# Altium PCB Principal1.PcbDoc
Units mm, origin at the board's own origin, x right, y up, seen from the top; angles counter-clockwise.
Board outline 152.4 x 101.6 mm, 2 copper layers (Top Layer, Bottom Layer); 36 components, 54 nets, 182 pads, 5 vias.
Unrouted connection lines stored in the file: 82.
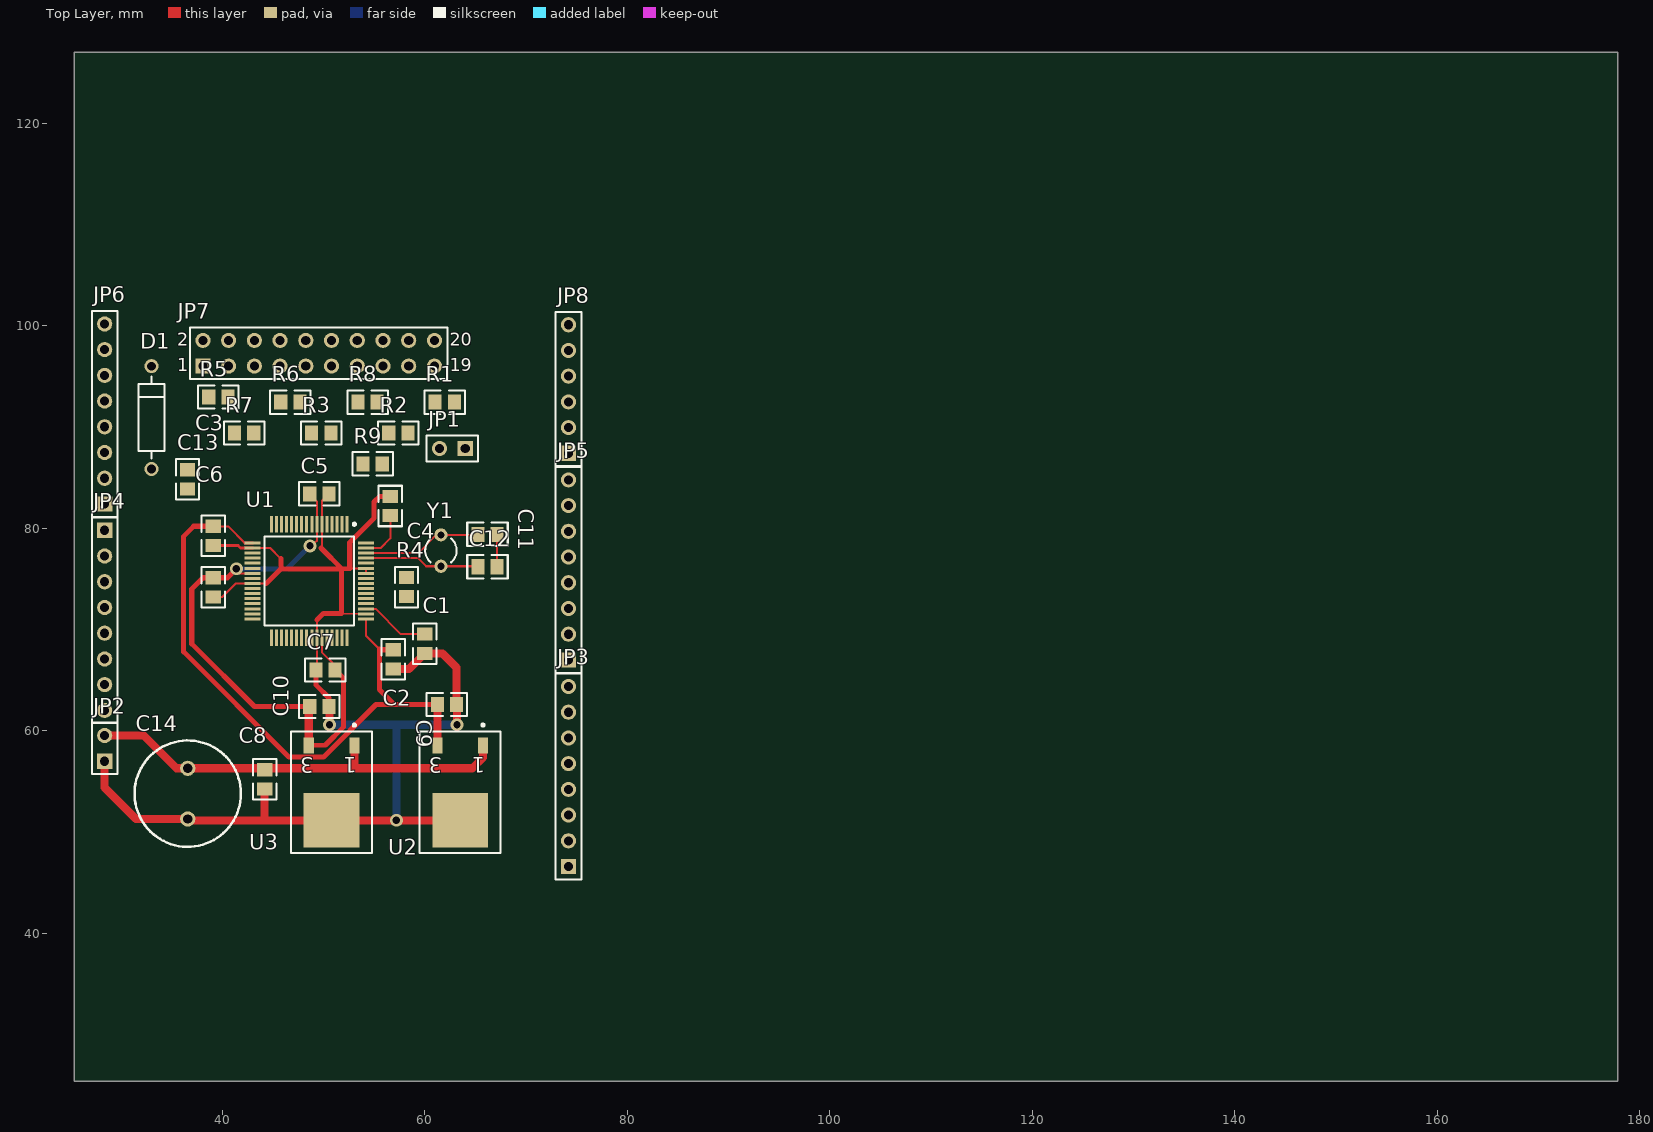
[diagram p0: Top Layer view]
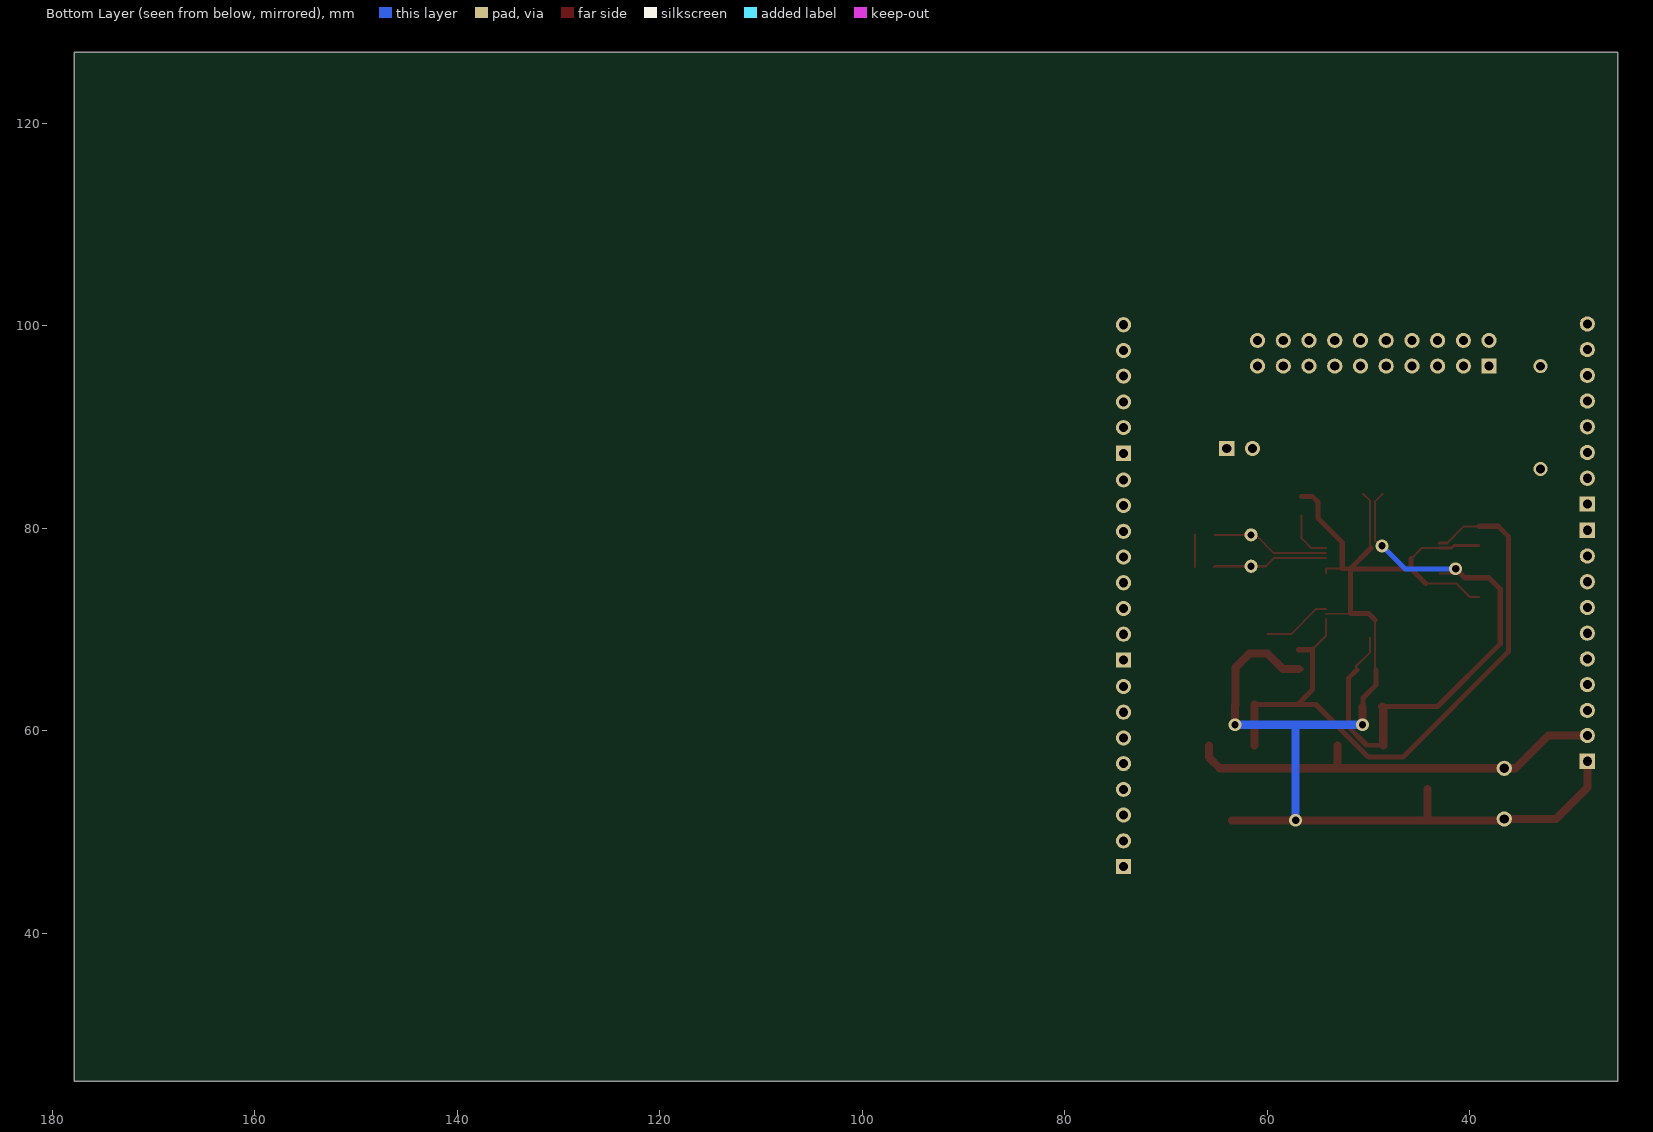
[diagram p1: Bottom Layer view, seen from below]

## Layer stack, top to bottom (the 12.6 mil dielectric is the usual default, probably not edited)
Top Layer: signal copper 0.0356
Dielectric: dielectric 0.32, FR-4, Dk 4.8
Bottom Layer: signal copper 0.0356

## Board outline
25.4,25.4 177.8,25.4 177.8,127 25.4,127

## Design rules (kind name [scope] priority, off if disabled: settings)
Clearance [All] p1: gap=0.1
ComponentClearance [All] p1: gap=0.254 collisioncheckmode=0
PolygonConnect [All] p1: connectstyle=Relief reliefconductorwidth=0.254 reliefentries=4 polygonreliefangle="90 Angle"
RoomDefinition Principal [InComponentClass('Principal')] p1: confinementstyle=ConfineIn formatcopy=TRUE outline 26.416,35.052 140.716,35.052 140.716,122.936 26.416,122.936
RoutingLayers [All] p1: top layer=Horizontal bottom layer=Vertical
RoutingVias [All] p1: holewidth=0.711 width=1.27 viastyle="Through Hole" minholewidth=0.711 minwidth=1.27 maxholewidth=0.711 maxwidth=1.27
SolderMaskExpansion [All] p1: expansion=0.102
TestPointUsage [All] p1: valid=0 allowmultiple=FALSE
Testpoint [All] p1: side=15 testpointundercomponent=TRUE minsize=1.016 maxsize=2.54 preferedsize=1.524 minholesize=0 maxholesize=1.016 preferedholesize=0.813 testpointgrid=0.025 style=1023 order=-539222988
Width [All] p1: maxlimit=0.8 minlimit=0.2 preferedwidth=0.2 bottomlayer_prefwidth=0.8 minimp=50.000000 maximp=50.000000 favimp=50.000000
16 further rules are at their usual default settings.

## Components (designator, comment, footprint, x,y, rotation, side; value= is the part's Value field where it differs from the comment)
C1 "Cap" R2012-0805 56.6,82.2 r270 top
C2 "Cap" R2012-0805 56.896,67.056 r90 top
C3 "Cap" R2012-0805 39.116,79.248 r90 top
C4 "Cap" R2012-0805 60,68.6 r90 top
C5 "Cap" R2012-0805 49.6,83.4 r180 top
C6 "Cap" R2012-0805 39.116,74.168 r90 top
C7 "Cap" R2012-0805 50.2,66 r0 top
C8 "Cap" R2012-0805 44.2,55.2 r90 top
C9 "Cap" R2012-0805 62.2,62.6 r180 top
C10 "Cap" R2012-0805 49.6,62.4 r180 top
C11 "Cap" R2012-0805 66.2,79.4 r0 top
C12 "Cap" R2012-0805 66.2,76.2 r0 top
C13 "Cap" R2012-0805 36.576,84.836 r270 top
C14 "Cap Pol1" RB5-10.5 36.6,53.8 r270 top
D1 "Diode" DIODE-0.4 33.02,90.932 r90 top
JP1 "JTAG" HDR1X2 64.008,87.884 r180 top
JP2 "Header 2" HDR1X2 28.4,57 r90 top
JP3 "Header 8" HDR1X8 74.2,46.6 r90 top
JP4 "Header 8" HDR1X8 28.4,79.8 r270 top
JP5 "Header 8" HDR1X8 74.2,67 r90 top
JP6 "Header 8" HDR1X8 28.4,82.4 r90 top
JP7 "JTAG P5" HDR2X10 38.1,96.012 r0 top
JP8 "Header 6" HDR1X6 74.2,87.4 r90 top
R1 "Res1" R2012-0805 61.976,92.456 r0 top
R2 "Res1" R2012-0805 57.404,89.408 r180 top
R3 "Res1" R2012-0805 49.784,89.408 r180 top
R4 "Res1" R2012-0805 58.2,74.2 r90 top
R5 "Res1" R2012-0805 39.624,92.964 r0 top
R6 "Res1" R2012-0805 46.736,92.456 r180 top
R7 "Res1" R2012-0805 42.164,89.408 r0 top
R8 "Res1" R2012-0805 54.356,92.456 r180 top
R9 "Res1" R2012-0805 54.864,86.36 r180 top
U1 "LPC2114/LPC2124" F-QFP10X10-G64/N 48.6,74.8 r270 top
U2 "LD1117S18" SIP-G3/C7.4 63.5,54.864 r180 top
U3 "LD1117S33" SIP-G3/C7.4 50.8,54.864 r180 top
Y1 "XTAL 16Mhz" BCY-W2/D3.1 61.6,77.8 r180 top

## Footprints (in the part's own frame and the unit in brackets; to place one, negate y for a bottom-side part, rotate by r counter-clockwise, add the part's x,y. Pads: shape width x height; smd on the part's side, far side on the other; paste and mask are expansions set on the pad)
BCY-W2/D3.1 [mm]
  round 1.3 hole 0.7: 1(0,1.55) 2(0,-1.55)
  silkscreen extent -1.55,-1.19 1.55,1.17
DIODE-0.4 [mm]
  round 1.4 hole 0.85: 1(-5.08,0) 2(5.08,0)
  silkscreen extent -4.06,-1.27 4.06,1.27
F-QFP10X10-G64/N [mm]
  rect 1.6x0.3 smd: 1(-5.6,3.75) 2(-5.6,3.25) 3(-5.6,2.75) 4(-5.6,2.25) 5(-5.6,1.75) 6(-5.6,1.25) 7(-5.6,0.75) 8(-5.6,0.25) 9(-5.6,-0.25) 10(-5.6,-0.75) 11(-5.6,-1.25) 12(-5.6,-1.75) 13(-5.6,-2.25) 14(-5.6,-2.75) 15(-5.6,-3.25) 16(-5.6,-3.75) 33(5.6,-3.75) 34(5.6,-3.25) 35(5.6,-2.75) 36(5.6,-2.25) 37(5.6,-1.75) 38(5.6,-1.25) 39(5.6,-0.75) 40(5.6,-0.25) 41(5.6,0.25) 42(5.6,0.75) 43(5.6,1.25) 44(5.6,1.75) 45(5.6,2.25) 46(5.6,2.75) 47(5.6,3.25) 48(5.6,3.75)
  rect 0.3x1.6 smd: 17(-3.75,-5.6) 18(-3.25,-5.6) 19(-2.75,-5.6) 20(-2.25,-5.6) 21(-1.75,-5.6) 22(-1.25,-5.6) 23(-0.75,-5.6) 24(-0.25,-5.6) 25(0.25,-5.6) 26(0.75,-5.6) 27(1.25,-5.6) 28(1.75,-5.6) 29(2.25,-5.6) 30(2.75,-5.6) 31(3.25,-5.6) 32(3.75,-5.6) 49(3.75,5.6) 50(3.25,5.6) 51(2.75,5.6) 52(2.25,5.6) 53(1.75,5.6) 54(1.25,5.6) 55(0.75,5.6) 56(0.25,5.6) 57(-0.25,5.6) 58(-0.75,5.6) 59(-1.25,5.6) 60(-1.75,5.6) 61(-2.25,5.6) 62(-2.75,5.6) 63(-3.25,5.6) 64(-3.75,5.6)
  silkscreen extent -5.72,-4.4 4.4,4.58
HDR1X2 [mm]
  rect 1.5x1.5 hole 0.9: 1(0,0)
  round 1.5 hole 0.9: 2(2.54,0)
  silkscreen extent -1.27,-1.27 3.81,1.27
HDR1X6 [mm]
  rect 1.5x1.5 hole 0.9: 1(0,0)
  round 1.5 hole 0.9: 2(2.54,0) 3(5.08,0) 4(7.62,0) 5(10.16,0) 6(12.7,0)
  silkscreen extent -1.27,-1.27 13.97,1.27
HDR1X8 [mm]
  rect 1.5x1.5 hole 0.9: 1(0,0)
  round 1.5 hole 0.9: 2(2.54,0) 3(5.08,0) 4(7.62,0) 5(10.16,0) 6(12.7,0) 7(15.24,0) 8(17.78,0)
  silkscreen extent -1.27,-1.27 19.05,1.27
HDR2X10 [mm]
  rect 1.5x1.5 hole 0.9: 1(0,0)
  round 1.5 hole 0.9: 2(0,2.54) 3(2.54,0) 4(2.54,2.54) 5(5.08,0) 6(5.08,2.54) 7(7.62,0) 8(7.62,2.54) 9(10.16,0) 10(10.16,2.54) 11(12.7,0) 12(12.7,2.54) 13(15.24,0) 14(15.24,2.54) 15(17.78,0) 16(17.78,2.54) 17(20.32,0) 18(20.32,2.54) 19(22.86,0) 20(22.86,2.54)
  silkscreen extent -1.27,-1.27 24.13,3.81
R2012-0805 [mm]
  rect 1.3x1.5 smd: 1(-0.95,0) 2(0.95,0)
  silkscreen extent -2,-1.15 2,1.15
RB5-10.5 [mm]
  round 1.5 hole 0.9: 1(-2.5,0) 2(2.5,0)
  silkscreen extent -5.25,-5.25 5.25,5.25
SIP-G3/C7.4 [mm]
  rect 1x1.6 smd: 1(-2.25,-3.7) 3(2.25,-3.7)
  rect 5.5x5.4 smd: 4(0,3.7)
  silkscreen extent -4,-5.82 4,6.95

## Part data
C1 C2 C3 C4 C5 C6 C7 C8 C9 C10 C11 C12 C13: "Capacitor"
C14: "Polarized Capacitor (Radial)"
D1: "Default Diode"
JP1: library part "Header 2", "Header, 2-Pin"
JP2: "Header, 2-Pin"
JP3 JP4 JP5 JP6: "Header, 8-Pin"
JP7: library part "Header 10X2", "Header, 10-Pin, Dual row"
JP8: "Header, 6-Pin"
R1 R2 R3 R4 R5 R6 R7 R8 R9: "Resistor"
U2 U3: library part LF27ACDT, "Very Low Drop Voltage Regulator with Inhibit"
Y1: library part XTAL, "Crystal Oscillator"

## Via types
v1: diameter 1.27, hole 0.711, Top Layer to Bottom Layer, 5 vias

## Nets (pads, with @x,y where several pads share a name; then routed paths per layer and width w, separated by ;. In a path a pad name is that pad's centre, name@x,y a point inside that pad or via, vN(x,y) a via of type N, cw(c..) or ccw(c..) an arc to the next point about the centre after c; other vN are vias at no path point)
GND: C1.1 C2.1 C3.1 C4.1 C5.1 C6.1 C7.1 C8.1 C9.1 C10.1 C11.2 C12.2 C13.2 C14.2 JP1.1 JP2.1 JP7.4 JP7.6 JP7.8 JP7.10 JP7.12 JP7.14 JP7.16 JP7.18 JP7.20 R1.2 R2.2 R3.2 U1.6 U1.18 U1.25 U1.42 U1.50 U1.58 U1.59 U2.4 U3.4 | length 143.9
  Top Layer w0.2: C6.1 40.018,73.218 41.35,74.55 44.35,74.55 ; U1.18 44.75,78.05 45.8,77 ; C7.1@49.342,66.04 49.35,66.048 49.35,70.95 ; 49.85,77.95 49.85,82.7 C5.1 ; 51.8,71.6 U1.50 ; 52.6,76.05 U1.59 U1.58 ; C2.1@56.494,66.106 C2.1 ; C12.2 C11.2
  Top Layer w0.254: C3.1 41.571,78.298 41.819,78.05 U1.18
  Top Layer w0.5: 44.35,74.55 45.8,76 ; 45.8,77 45.8,76 ; C7.1 49.25,64.55 50.55,63.25 C10.1 ; 49.35,70.95 50,71.6 51.8,71.6 51.8,76 ; 49.75,78.05 49.85,77.95 51.8,76 ; C1.1 55.55,83.15 55,82.6 55,81 52.6,78.6 52.6,76.05 51.8,76 ; 45.8,76 51.8,76
  Top Layer w0.8: JP2.1 28.4,54.4 31.5,51.3 C14.2 36.736,51.164 U2.4 ; 44.2,51.364 C8.1 ; v1(50.6,60.6) C10.1@50.6,62.35 ; C2.1 58.456,66.106 C4.1 61.75,67.65 63.15,66.25 C9.1 ; v1(63.2,60.6) C9.1@63.2,62.55
  Bottom Layer w0.8: v1(50.6,60.6) v1(63.2,60.6) ; v1(57.2,51.164) 57.2,60.6
NetC1_2: C1.2 C2.2 C3.2 C9.2 U1.17 U1.49 U1.63 U2.3 | length 70.9
  Top Layer w0.2: C3.2 40.602,80.198 U1.17@42.25,78.55 ; U1.49 54.2,69.4 55.521,68.079 ; U1.63 55.65,78.05 56.6,79 C1.2
  Top Layer w0.254: U1.17@42.25,78.55 U1.17
  Top Layer w0.5: C3.2 37.198,80.198 36.2,79.2 36.2,67.8 46.6,57.4 50,57.4 55.2,62.6 C9.2 ; C2.2 55.594,68.006 55.521,68.079 55.521,64.079 57,62.6
  Top Layer w0.8: U2.3 C9.2
NetC4_2: C4.2 C5.2 C6.2 C7.2 C10.2 D1.2 JP7.1 JP7.2 R5.1 R6.1 R7.1 R8.1 R9.2 U1.7 U1.23 U1.43 U1.51 U3.3 | length 65.5
  Top Layer w0.2: 40.95,75.55 U1.23 ; C5.2 48.65,83.35 49.35,82.65 49.35,78.75 48.867,78.267 v1(48.667,78.267) ; U1.43 49.85,67.75 51.242,66.358 C7.2@51.242,66.04 ; U1.51 55.15,72.05 57.65,69.55 C4.2
  Top Layer w0.5: v1(41.4,76) 40.518,75.118 38.118,75.118 37,74 37,68.6 43.2,62.4 C10.2 ; U3.3 50.2,58.6 52,60.4 52,65.2 C7.2
  Top Layer w0.8: U3.3 48.55,62.3 C10.2
  Bottom Layer w0.5: v1(41.4,76) 46.4,76 v1(48.667,78.267)
NetC8_2: C8.2 C14.1 JP2.2 U2.1 U3.1 | length 42.6
  Top Layer w0.8: JP2.2 32.26,59.54 35.5,56.3 64.7,56.3 65.75,57.35 U2.1 ; 53.05,56.35 U3.1
NetC11_1: C11.1 U1.62 Y1.2 | length 11.7
  Top Layer w0.2: U1.62 59.35,77.55 61.15,79.35 C11.1@65.2,79.35
NetC12_1: C12.1 U1.61 Y1.1 | length 11.4
  Top Layer w0.2: U1.61 59.35,77.05 60.15,76.25 65.2,76.25 C12.1
NetC13_1: C13.1 D1.1 JP7.15 R9.1 U1.57
NetJP1_2: JP1.2 R4.2
NetJP3_1: JP3.1 U1.36
NetJP3_2: JP3.2 U1.40
NetJP3_3: JP3.3 U1.44
NetJP3_4: JP3.4 U1.48
NetJP3_5: JP3.5 U1.4
NetJP3_6: JP3.6 U1.8
NetJP3_7: JP3.7 U1.12
NetJP3_8: JP3.8 U1.16
NetJP4_1: JP4.1 U1.19
NetJP4_2: JP4.2 U1.21
NetJP4_3: JP4.3 U1.22
NetJP4_4: JP4.4 U1.26
NetJP4_5: JP4.5 U1.27
NetJP4_6: JP4.6 U1.29
NetJP4_7: JP4.7 U1.30
NetJP4_8: JP4.8 U1.31
NetJP5_1: JP5.1 U1.33
NetJP5_2: JP5.2 U1.34
NetJP5_3: JP5.3 U1.35
NetJP5_4: JP5.4 U1.37
NetJP5_5: JP5.5 U1.38
NetJP5_6: JP5.6 U1.39
NetJP5_7: JP5.7 U1.41
NetJP5_8: JP5.8 U1.45
NetJP6_1: JP6.1 U1.46
NetJP6_2: JP6.2 U1.47
NetJP6_3: JP6.3 U1.53
NetJP6_4: JP6.4 U1.54
NetJP6_5: JP6.5 U1.55
NetJP6_6: JP6.6 U1.1
NetJP6_7: JP6.7 U1.2
NetJP6_8: JP6.8 U1.3
NetJP7_3: JP7.3 R5.2 U1.20
NetJP7_5: JP7.5 R7.2 U1.60
NetJP7_7: JP7.7 R6.2 U1.52
NetJP7_9: JP7.9 R4.1 U1.56
NetJP7_11: JP7.11 R3.1 U1.24
NetJP7_13: JP7.13 R8.2 U1.64
NetJP7_17: JP7.17 R2.1
NetJP7_19: JP7.19 R1.1
NetJP8_1: JP8.1 U1.5
NetJP8_2: JP8.2 U1.9
NetJP8_3: JP8.3 U1.11
NetJP8_4: JP8.4 U1.13
NetJP8_5: JP8.5 U1.14
NetJP8_6: JP8.6 U1.15
pads on no net: U1.10 U1.28 U1.32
